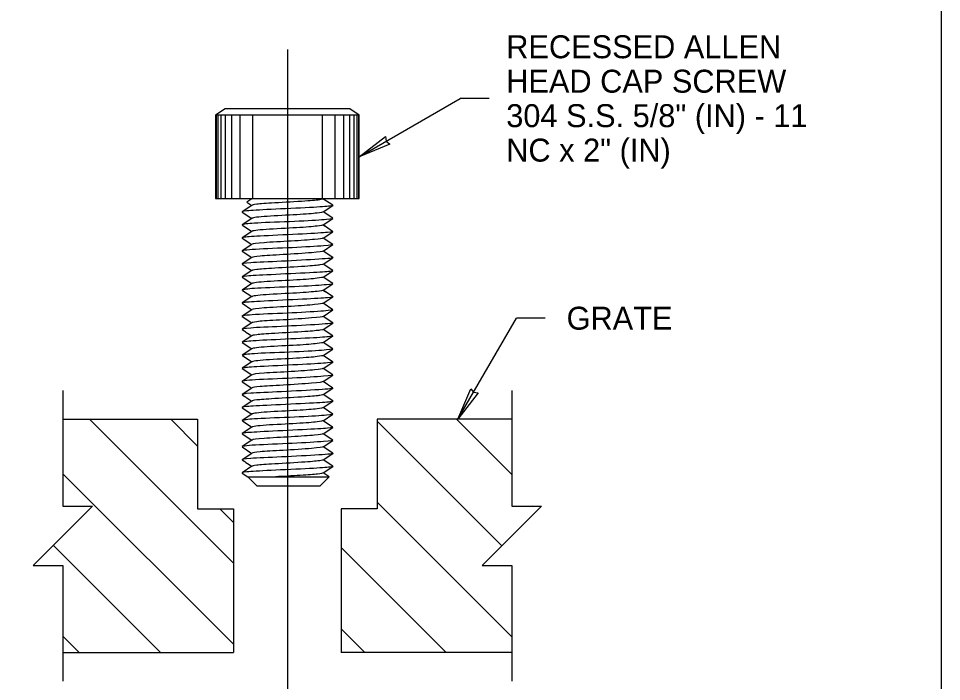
# Model space of a CAD drawing. Extents: x 99862 to 103151, y 100000 to 102076.
# Drawn here: x 102508 to 103151, y 101158 to 101620 of the extents above; entities that cross this region are included whole.
import ezdxf

# ---------------------------------------------------------------- set-up
doc = ezdxf.new("R2010")
doc.units = 0
for name, color, linetype in [('Level 1', 7, 'Continuous'), ('Level 14', 7, 'Continuous'), ('Level 15', 7, 'Continuous'), ('Level 17', 7, 'Continuous'), ('Level 2', 7, 'Continuous'), ('Level 20', 7, 'Continuous')]:
    doc.layers.add(name, color=color, linetype=linetype)

msp = doc.modelspace()

# ---------------------------------------------------------------- linework, layer by layer
at = {"layer": 'Level 1'}
msp.add_lwpolyline([(99862, 99999.5), (103151, 99999.5), (103151, 102075.5), (99862, 102075.5)], close=True, dxfattribs=at)
at = {"layer": 'Level 14'}
for p, q in [((102652.14, 101556.63), (102645.55, 101552.22)), ((102745.55, 101552.22), (102738.97, 101556.63)), ((102745.55, 101552.22), (102645.55, 101552.22)), ((102645.95, 101552.22), (102645.95, 101494.13)), ((102647.14, 101552.22), (102647.14, 101494.13)), ((102649.2, 101552.22), (102649.2, 101494.13)), ((102652.25, 101552.22), (102652.25, 101494.13)), ((102656.52, 101552.22), (102656.52, 101494.13)), ((102662.48, 101552.22), (102662.48, 101494.13)), ((102671.35, 101552.22), (102671.35, 101494.13)), ((102719.76, 101552.22), (102719.76, 101494.13)), ((102728.63, 101552.22), (102728.63, 101494.13)), ((102734.58, 101552.22), (102734.58, 101494.13)), ((102738.86, 101552.22), (102738.86, 101494.13)), ((102741.9, 101552.22), (102741.9, 101494.13)), ((102743.97, 101552.22), (102743.97, 101494.13)), ((102745.16, 101552.22), (102745.16, 101494.13)), ((102670.76, 101489.32), (102664.11, 101484.86)), ((102670.76, 101493.95), (102667.27, 101491.62)), ((102720.29, 101493.95), (102670.76, 101493.95)), ((102727.12, 101489.37), (102720.29, 101493.95)), ((102664.11, 101484.64), (102670.7, 101480.23)), ((102720.45, 101484.75), (102727.12, 101489.23)), ((102727.12, 101480.28), (102720.45, 101484.75)), ((102670.7, 101480.23), (102663.99, 101475.77)), ((102720.39, 101475.66), (102727.12, 101480.13)), ((102670.73, 101471.16), (102664.05, 101466.75)), ((102664.18, 101475.55), (102670.73, 101471.16)), ((102727.06, 101471.19), (102720.39, 101475.66)), ((102720.45, 101466.57), (102727.12, 101470.97)), ((102664.05, 101466.53), (102670.75, 101462.04)), ((102727.12, 101462.1), (102720.45, 101466.57)), ((102670.75, 101462.04), (102664.05, 101457.59)), ((102664.05, 101457.37), (102670.73, 101452.89)), ((102720.4, 101457.44), (102727.12, 101461.95)), ((102727.12, 101452.93), (102720.4, 101457.44)), ((102670.73, 101452.89), (102664.11, 101448.5)), ((102720.5, 101448.35), (102727.12, 101452.79)), ((102727.12, 101443.92), (102720.5, 101448.35)), ((102670.76, 101443.86), (102664.11, 101439.41)), ((102664.11, 101439.19), (102670.7, 101434.77)), ((102720.45, 101439.3), (102727.12, 101443.77)), ((102727.12, 101434.83), (102720.45, 101439.3)), ((102670.7, 101434.77), (102663.99, 101430.32)), ((102720.39, 101430.21), (102727.12, 101434.68)), ((102670.73, 101425.7), (102664.05, 101421.3)), ((102664.18, 101430.1), (102670.73, 101425.7)), ((102727.06, 101425.73), (102720.39, 101430.21)), ((102720.45, 101421.12), (102727.12, 101425.52)), ((102664.05, 101421.08), (102670.75, 101416.59)), ((102727.12, 101416.64), (102720.45, 101421.12)), ((102670.75, 101416.59), (102664.05, 101412.13)), ((102720.4, 101411.99), (102727.12, 101416.5)), ((102664.05, 101411.92), (102670.73, 101407.44)), ((102670.73, 101407.44), (102664.11, 101403.04)), ((102727.12, 101407.48), (102720.4, 101411.99)), ((102720.5, 101402.9), (102727.12, 101407.33)), ((102727.12, 101398.46), (102720.5, 101402.9)), ((102670.76, 101398.41), (102664.11, 101393.95)), ((102664.11, 101393.73), (102670.7, 101389.32)), ((102720.45, 101393.84), (102727.12, 101398.32)), ((102727.12, 101389.37), (102720.45, 101393.84)), ((102670.7, 101389.32), (102663.99, 101384.86)), ((102720.39, 101384.75), (102727.12, 101389.23)), ((102670.73, 101380.25), (102664.05, 101375.84)), ((102664.18, 101384.64), (102670.73, 101380.25)), ((102727.06, 101380.28), (102720.39, 101384.75)), ((102720.45, 101375.66), (102727.12, 101380.06)), ((102664.05, 101375.63), (102670.75, 101371.13)), ((102727.12, 101371.19), (102720.45, 101375.66)), ((102670.75, 101371.13), (102664.05, 101366.68)), ((102720.4, 101366.53), (102727.12, 101371.04)), ((102664.05, 101366.46), (102670.73, 101361.98)), ((102670.73, 101361.98), (102664.11, 101357.59)), ((102727.12, 101362.03), (102720.4, 101366.53)), ((102720.5, 101357.44), (102727.12, 101361.88)), ((102727.12, 101353.01), (102720.5, 101357.44)), ((102670.76, 101352.95), (102664.11, 101348.5)), ((102664.11, 101348.28), (102670.7, 101343.87)), ((102720.45, 101348.39), (102727.12, 101352.86)), ((102727.12, 101343.92), (102720.45, 101348.39)), ((102670.7, 101343.87), (102663.99, 101339.41)), ((102720.39, 101339.3), (102727.12, 101343.77)), ((102664.18, 101339.19), (102670.73, 101334.8)), ((102727.06, 101334.83), (102720.39, 101339.3)), ((102670.73, 101334.8), (102664.05, 101330.39)), ((102664.05, 101330.17), (102670.75, 101325.68)), ((102720.45, 101330.21), (102727.12, 101334.61)), ((102727.12, 101325.73), (102720.45, 101330.21)), ((102670.75, 101325.68), (102664.05, 101321.23)), ((102720.4, 101321.08), (102727.12, 101325.59)), ((102664.05, 101321.01), (102670.73, 101316.53)), ((102670.73, 101316.53), (102664.11, 101312.13)), ((102727.12, 101316.57), (102720.4, 101321.08)), ((102720.5, 101311.99), (102727.12, 101316.43)), ((102727.12, 101307.55), (102720.5, 101311.99)), ((102670.76, 101307.5), (102664.11, 101303.04)), ((102720.45, 101302.93), (102727.12, 101307.41)), ((102724.52, 101300.2), (102720.45, 101302.93)), ((102664.11, 101302.83), (102668.03, 101300.2)), ((102668.03, 101300.2), (102724.52, 101300.2)), ((102674.28, 101293.95), (102668.03, 101300.2)), ((102718.27, 101293.95), (102724.52, 101300.2))]:
    msp.add_line(p, q, dxfattribs=at)
for points in [[(102738.97, 101556.63), (102652.14, 101556.63)], [(102645.55, 101552.22), (102645.55, 101494.13), (102671.35, 101494.13)], [(102745.55, 101494.13), (102745.55, 101552.22)], [(102667.27, 101491.62), (102670.76, 101489.32)], [(102720.55, 101494.13), (102745.55, 101494.13)], [(102720.48, 101475.6), (102722, 101474.61)], [(102664.11, 101448.28), (102665.82, 101447.12), (102666.46, 101446.75), (102666.71, 101446.53), (102670.76, 101443.86)], [(102720.48, 101430.15), (102722, 101429.15)], [(102664.11, 101402.83), (102665.82, 101401.66), (102666.46, 101401.3), (102666.71, 101401.08), (102670.76, 101398.41)], [(102720.48, 101384.7), (102722, 101383.7)], [(102664.11, 101357.37), (102665.82, 101356.21), (102666.46, 101355.84), (102666.71, 101355.63), (102670.76, 101352.95)], [(102720.48, 101339.24), (102722, 101338.24)], [(102664.11, 101311.92), (102665.82, 101310.75), (102666.46, 101310.39), (102666.71, 101310.17), (102670.76, 101307.5)], [(102674.28, 101293.95), (102718.27, 101293.95)]]:
    msp.add_lwpolyline(points, dxfattribs=at)
for points in [[(102727.12, 101489.37), (102727.25, 101489.3), (102727.12, 101488.79), (102714.4, 101487.84), (102681.45, 101486.39), (102664.81, 101485.44), (102663.86, 101484.79), (102664.11, 101484.64)], [(102720.29, 101493.73), (102720.29, 101493.73), (102719.59, 101493.3), (102710.36, 101492.35), (102684.55, 101490.9), (102672.53, 101490.1), (102671.07, 101489.52), (102670.95, 101489.44)], [(102720.22, 101484.64), (102720.1, 101484.57), (102718.01, 101483.99), (102703.78, 101482.75), (102679.3, 101481.73), (102671.52, 101480.72), (102670.88, 101480.35)], [(102727.12, 101480.28), (102727.37, 101480.13), (102725.47, 101479.55), (102705.99, 101478.17), (102673.67, 101477.15), (102663.55, 101476.06), (102663.93, 101475.55), (102663.99, 101475.55)], [(102727.12, 101471.19), (102727.37, 101471.04), (102726.04, 101470.46), (102708.65, 101469.44), (102675.88, 101467.92), (102663.86, 101467.12), (102663.93, 101466.61), (102664.05, 101466.53)], [(102720.22, 101475.55), (102720.1, 101475.48), (102718.01, 101474.9), (102703.78, 101473.66), (102678.47, 101472.57), (102670.76, 101471.55), (102670.76, 101471.12)], [(102720.22, 101466.46), (102719.91, 101466.24), (102716.56, 101465.66), (102698.91, 101464.35), (102677.02, 101463.33), (102671.45, 101462.53), (102670.95, 101462.17)], [(102727.12, 101462.1), (102727.5, 101461.88), (102723.89, 101461.23), (102699.79, 101459.77), (102670.12, 101458.68), (102663.42, 101457.81), (102664.05, 101457.37)], [(102720.35, 101457.44), (102720.41, 101457.08), (102714.72, 101456.43), (102691.57, 101454.83), (102674.49, 101454.03), (102671.33, 101453.3), (102671.01, 101453.08)], [(102727.12, 101452.93), (102727.69, 101452.57), (102720.67, 101451.92), (102690.43, 101450.24), (102666.9, 101449.37), (102663.67, 101448.57), (102664.11, 101448.28)], [(102720.29, 101448.28), (102720.29, 101448.28), (102719.59, 101447.84), (102710.36, 101446.9), (102684.55, 101445.44), (102672.53, 101444.64), (102671.07, 101444.06), (102670.95, 101443.99)], [(102727.12, 101443.92), (102727.25, 101443.84), (102727.12, 101443.33), (102714.4, 101442.39), (102681.45, 101440.93), (102664.81, 101439.99), (102663.86, 101439.33), (102664.11, 101439.19)], [(102720.22, 101439.19), (102720.1, 101439.12), (102718.01, 101438.53), (102703.78, 101437.3), (102679.3, 101436.28), (102671.52, 101435.26), (102670.88, 101434.9)], [(102727.12, 101434.83), (102727.37, 101434.68), (102725.47, 101434.1), (102705.99, 101432.72), (102673.67, 101431.7), (102663.55, 101430.61), (102663.93, 101430.1), (102663.99, 101430.1)], [(102727.12, 101425.73), (102727.37, 101425.59), (102726.04, 101425.01), (102708.65, 101423.99), (102675.88, 101422.46), (102663.86, 101421.66), (102663.93, 101421.15), (102664.05, 101421.08)], [(102720.22, 101430.1), (102720.1, 101430.03), (102718.01, 101429.44), (102703.78, 101428.21), (102678.47, 101427.12), (102670.76, 101426.1), (102670.76, 101425.66)], [(102720.22, 101421.01), (102719.91, 101420.79), (102716.56, 101420.21), (102698.91, 101418.9), (102677.02, 101417.88), (102671.45, 101417.08), (102670.95, 101416.72)], [(102727.12, 101416.64), (102727.5, 101416.43), (102723.89, 101415.77), (102699.79, 101414.32), (102670.12, 101413.23), (102663.42, 101412.35), (102664.05, 101411.92)], [(102727.12, 101407.48), (102727.69, 101407.12), (102720.67, 101406.46), (102690.43, 101404.79), (102666.9, 101403.92), (102663.67, 101403.12), (102664.11, 101402.83)], [(102720.35, 101411.99), (102720.41, 101411.63), (102714.72, 101410.97), (102691.57, 101409.37), (102674.49, 101408.57), (102671.33, 101407.84), (102671.01, 101407.63)], [(102720.29, 101402.83), (102720.29, 101402.83), (102719.59, 101402.39), (102710.36, 101401.44), (102684.55, 101399.99), (102672.53, 101399.19), (102671.07, 101398.61), (102670.95, 101398.53)], [(102727.12, 101398.46), (102727.25, 101398.39), (102727.12, 101397.88), (102714.4, 101396.93), (102681.45, 101395.48), (102664.81, 101394.53), (102663.86, 101393.88), (102664.11, 101393.73)], [(102720.22, 101393.73), (102720.1, 101393.66), (102718.01, 101393.08), (102703.78, 101391.84), (102679.3, 101390.83), (102671.52, 101389.81), (102670.88, 101389.44)], [(102727.12, 101389.37), (102727.37, 101389.23), (102725.47, 101388.64), (102705.99, 101387.26), (102673.67, 101386.24), (102663.55, 101385.15), (102663.93, 101384.64), (102663.99, 101384.64)], [(102727.12, 101380.28), (102727.37, 101380.13), (102726.04, 101379.55), (102708.65, 101378.53), (102675.88, 101377.01), (102663.86, 101376.21), (102663.93, 101375.7), (102664.05, 101375.63)], [(102720.22, 101384.64), (102720.1, 101384.57), (102718.01, 101383.99), (102703.78, 101382.75), (102678.47, 101381.66), (102670.76, 101380.64), (102670.76, 101380.21)], [(102720.22, 101375.55), (102719.91, 101375.33), (102716.56, 101374.75), (102698.91, 101373.44), (102677.02, 101372.43), (102671.45, 101371.63), (102670.95, 101371.26)], [(102727.12, 101371.19), (102727.5, 101370.97), (102723.89, 101370.32), (102699.79, 101368.86), (102670.12, 101367.77), (102663.42, 101366.9), (102664.05, 101366.46)], [(102727.12, 101362.03), (102727.69, 101361.66), (102720.67, 101361.01), (102690.43, 101359.33), (102666.9, 101358.46), (102663.67, 101357.66), (102664.11, 101357.37)], [(102720.35, 101366.53), (102720.41, 101366.17), (102714.72, 101365.52), (102691.57, 101363.92), (102674.49, 101363.12), (102671.33, 101362.39), (102671.01, 101362.17)], [(102720.29, 101357.37), (102720.29, 101357.37), (102719.59, 101356.93), (102710.36, 101355.99), (102684.55, 101354.53), (102672.53, 101353.73), (102671.07, 101353.15), (102670.95, 101353.08)], [(102727.12, 101353.01), (102727.25, 101352.93), (102727.12, 101352.43), (102714.4, 101351.48), (102681.45, 101350.03), (102664.81, 101349.08), (102663.86, 101348.43), (102664.11, 101348.28)], [(102720.22, 101348.28), (102720.1, 101348.21), (102718.01, 101347.63), (102703.78, 101346.39), (102679.3, 101345.37), (102671.52, 101344.35), (102670.88, 101343.99)], [(102727.12, 101343.92), (102727.37, 101343.77), (102725.47, 101343.19), (102705.99, 101341.81), (102673.67, 101340.79), (102663.55, 101339.7), (102663.93, 101339.19), (102663.99, 101339.19)], [(102720.22, 101339.19), (102720.1, 101339.12), (102718.01, 101338.53), (102703.78, 101337.3), (102678.47, 101336.21), (102670.76, 101335.19), (102670.76, 101334.75)], [(102727.12, 101334.83), (102727.37, 101334.68), (102726.04, 101334.1), (102708.65, 101333.08), (102675.88, 101331.55), (102663.86, 101330.75), (102663.93, 101330.24), (102664.05, 101330.17)], [(102720.22, 101330.1), (102719.91, 101329.88), (102716.56, 101329.3), (102698.91, 101327.99), (102677.02, 101326.97), (102671.45, 101326.17), (102670.95, 101325.81)], [(102727.12, 101325.73), (102727.5, 101325.52), (102723.89, 101324.86), (102699.79, 101323.41), (102670.12, 101322.32), (102663.42, 101321.44), (102664.05, 101321.01)], [(102727.12, 101316.57), (102727.69, 101316.21), (102720.67, 101315.55), (102690.43, 101313.88), (102666.9, 101313.01), (102663.67, 101312.21), (102664.11, 101311.92)], [(102720.35, 101321.08), (102720.41, 101320.72), (102714.72, 101320.06), (102691.57, 101318.46), (102674.49, 101317.66), (102671.33, 101316.93), (102671.01, 101316.72)], [(102720.29, 101311.92), (102720.29, 101311.92), (102719.59, 101311.48), (102710.36, 101310.53), (102684.55, 101309.08), (102672.53, 101308.28), (102671.07, 101307.7), (102670.95, 101307.63)], [(102727.12, 101307.55), (102727.25, 101307.48), (102727.12, 101306.97), (102714.4, 101306.03), (102681.45, 101304.57), (102664.81, 101303.63), (102663.86, 101302.97), (102664.11, 101302.83)], [(102720.22, 101302.83), (102720.1, 101302.75), (102718.01, 101302.17), (102705.84, 101301.11), (102692.34, 101300.47), (102687.45, 101300.2)]]:
    msp.add_open_spline(points, degree=3, dxfattribs=at)
at = {"layer": 'Level 15'}
for p, q in [((102695.55, 101597.87), (102695.55, 100942.88)), ((102745.55, 101523.17), (102815.92, 101563.8)), ((102835.92, 101563.8), (102815.92, 101563.8)), ((102814.32, 101340.32), (102854.95, 101410.68)), ((102874.95, 101410.68), (102854.95, 101410.68))]:
    msp.add_line(p, q, dxfattribs=at)
for points in [[(102745.55, 101523.17), (102763.83, 101537.17), (102764.41, 101534.06), (102766.82, 101532)], [(102814.32, 101340.32), (102823.15, 101361.58), (102825.21, 101359.17), (102828.32, 101358.59)]]:
    msp.add_lwpolyline(points, close=True, dxfattribs=at)
for points in [[(102539.29, 101360.32), (102539.29, 101279.71), (102559.94, 101279.71), (102518.64, 101238.42), (102539.29, 101238.42), (102539.29, 101157.82)], [(102851.82, 101360.32), (102851.82, 101279.71), (102872.47, 101279.71), (102831.17, 101238.42), (102851.82, 101238.42), (102851.82, 101157.82)]]:
    msp.add_lwpolyline(points, dxfattribs=at)
at = {"layer": 'Level 17'}
for p, q in [((102658.05, 101240.05), (102557.79, 101340.32)), ((102633.05, 101321.62), (102614.36, 101340.32)), ((102844.91, 101252.15), (102758.05, 101339)), ((102851.82, 101301.8), (102813.31, 101340.32)), ((102658.05, 101183.48), (102539.29, 101302.25)), ((102658.05, 101268.33), (102648.57, 101277.82)), ((102851.82, 101188.67), (102758.05, 101282.43)), ((102607.15, 101177.82), (102532.59, 101252.37)), ((102806.1, 101177.82), (102733.05, 101250.87)), ((102749.53, 101177.82), (102733.05, 101194.3)), ((102550.58, 101177.82), (102539.29, 101189.11))]:
    msp.add_line(p, q, dxfattribs=at)
at = {"layer": 'Level 2'}
for p, q in [((102539.29, 101340.32), (102633.05, 101340.32)), ((102633.05, 101340.32), (102633.05, 101277.82)), ((102758.05, 101340.32), (102758.05, 101277.82)), ((102851.82, 101340.32), (102758.05, 101340.32)), ((102633.05, 101277.82), (102658.05, 101277.82)), ((102658.05, 101277.82), (102658.05, 101177.82)), ((102758.05, 101277.82), (102733.05, 101277.82)), ((102733.05, 101277.82), (102733.05, 101177.82)), ((102539.29, 101177.82), (102658.05, 101177.82)), ((102851.82, 101177.82), (102733.05, 101177.82))]:
    msp.add_line(p, q, dxfattribs=at)

# ---------------------------------------------------------------- texts
at = {"layer": 'Level 20'}
for s, p in [('RECESSED ALLEN', (102847.92, 101591.8)), ('HEAD CAP SCREW', (102847.92, 101567.8)), ('304 S.S. 5/8" (IN) - 11', (102847.92, 101543.8)), ('NC x 2" (IN)', (102847.92, 101519.8)), ('GRATE', (102889.94, 101402.69))]:
    msp.add_text(s, height=16, rotation=360, dxfattribs=at).set_placement(p)

doc.saveas('drawing.dxf')
